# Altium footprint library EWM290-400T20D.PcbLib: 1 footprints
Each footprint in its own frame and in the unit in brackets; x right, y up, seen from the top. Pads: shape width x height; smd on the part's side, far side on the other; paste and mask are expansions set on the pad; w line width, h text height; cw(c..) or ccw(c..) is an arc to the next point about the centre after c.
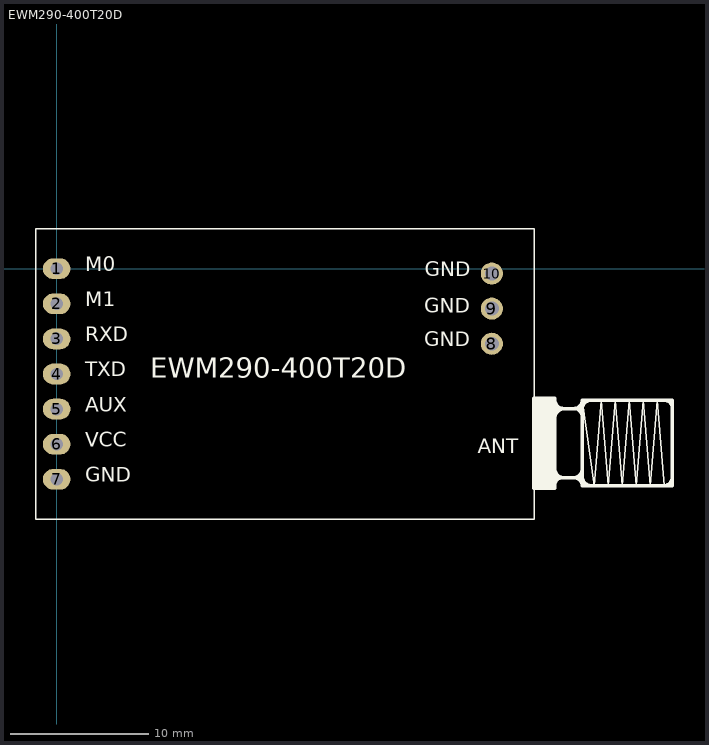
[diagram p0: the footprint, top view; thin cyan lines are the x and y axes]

## EWM290-400T20D [mm] "36mm*21mm-D/SMA长度12.5mm"
pads (10):
  oval 2x1.5 hole 0.9: 1(0,0) 2(0,-2.54) 3(0,-5.08) 4(0,-7.62) 5(0,-10.16) 6(0,-12.7) 7(0,-15.24)
  round 1.6 hole 1: 8(31.49,-5.43) 9(31.49,-2.89) 10(31.49,-0.35)
Top Overlay:
  rectangle: 34.54,-15.87 36.04,-9.37
  rectangle: 34.54,-15.865 36.04,-9.365
  lines w0.1: 38.89,-15.72 39.41,-9.52 ; 38.89,-15.72 38.04,-9.52 38.89,-15.72 ; 38.89,-15.72 39.41,-9.52 ; 39.41,-9.52 39.92,-15.72 ; 39.41,-9.52 39.92,-15.72 ; 39.92,-15.72 40.43,-9.52 ; 39.92,-15.72 40.43,-9.52 ; 40.43,-9.52 40.91,-15.72 ; 40.43,-9.52 40.91,-15.72 ; 40.91,-15.72 41.43,-9.52 ; 40.91,-15.72 41.43,-9.52 ; 41.43,-9.52 41.94,-15.72 ; 41.43,-9.52 41.94,-15.72 ; 41.94,-15.72 42.43,-9.52 ; 41.94,-15.72 42.43,-9.52 ; 42.43,-9.52 42.95,-15.72 ; 42.43,-9.52 42.95,-15.72 ; 42.95,-15.72 43.47,-9.52 ; 42.95,-15.72 43.47,-9.52 ; 43.47,-9.52 43.98,-15.72 43.47,-9.52 ; -1.51,-18.12 34.558,-18.12 34.558,2.88 -1.51,2.88 -1.51,-18.12
  lines w0.254: 34.54,-15.87 36.04,-15.87 ; 34.54,-15.87 34.54,-9.37 ; 34.54,-15.87 36.04,-15.87 ; 34.54,-15.87 34.54,-9.37 ; 34.54,-9.37 36.04,-9.37 ; 34.54,-9.37 36.04,-9.37 ; 36.04,-15.87 36.04,-9.37 ; 36.04,-15.87 36.04,-9.37 ; 36.04,-14.47 ccw(c36.69,-14.47) 36.69,-15.12 ; 36.04,-14.47 ccw(c36.69,-14.47) 36.69,-15.12 ; 36.04,-14.47 36.04,-14.1 36.04,-14.47 ; 36.04,-10.82 cw(c36.74,-10.82) 36.74,-10.12 ; 36.04,-10.82 cw(c36.74,-10.82) 36.74,-10.12 ; 36.04,-10.82 36.04,-11.74 36.04,-10.82 ; 36.04,-9.49 ccw(c36.67,-9.49) 36.67,-10.12 ; 36.04,-9.49 ccw(c36.67,-9.49) 36.67,-10.12 ; 36.04,-9.49 36.04,-9.37 ; 36.04,-9.49 36.04,-9.37 ; 36.59,-15.12 ccw(c36.59,-15.67) 36.04,-15.67 cw(c36.59,-15.67) 36.59,-15.12 ; 36.59,-15.12 37.44,-15.12 ; 36.59,-15.12 37.44,-15.12 ; 36.67,-10.12 37.44,-10.12 ; 36.67,-10.12 37.44,-10.12 ; 36.69,-15.12 37.41,-15.12 ; 36.69,-15.12 37.41,-15.12 ; 36.74,-10.12 37.44,-10.12 ; 36.74,-10.12 37.44,-10.12 ; 37.41,-15.12 ccw(c37.41,-14.49) 38.04,-14.49 cw(c37.41,-14.49) 37.41,-15.12 ; 37.44,-15.12 cw(c37.44,-15.72) 38.04,-15.72 ; 37.44,-15.12 cw(c37.44,-15.72) 38.04,-15.72 ; 37.44,-10.12 cw(c37.44,-10.72) 38.04,-10.72 ccw(c37.44,-10.72) 37.44,-10.12 ; 37.44,-10.12 ccw(c37.44,-9.52) 38.04,-9.52 ; 37.44,-10.12 ccw(c37.44,-9.52) 38.04,-9.52 ; 38.04,-15.72 38.04,-9.52 ; 38.04,-15.72 44.54,-15.72 ; 38.04,-15.72 38.04,-9.52 ; 38.04,-15.72 44.54,-15.72 ; 38.04,-9.52 44.54,-9.52 ; 38.04,-9.52 44.54,-9.52 ; 38.72,-15.72 cw(c38.72,-15.04) 38.04,-15.04 ccw(c38.72,-15.04) 38.72,-15.72 ; 38.72,-15.72 38.87,-15.72 38.72,-15.72 ; 43.92,-15.72 ccw(c43.92,-15.1) 44.54,-15.1 cw(c43.92,-15.1) 43.92,-15.72 ; 43.92,-15.72 43.69,-15.72 43.92,-15.72 ; 44,-9.52 cw(c44,-10.06) 44.54,-10.06 ccw(c44,-10.06) 44,-9.52 ; 44,-9.52 43.6,-9.52 44,-9.52 ; 44.54,-15.72 44.54,-9.52 ; 44.54,-15.72 44.54,-9.52 ; 35.87,-15.12 38.04,-15.12 35.87,-15.12 ; 36.04,-10.12 38.04,-10.12 36.04,-10.12 ; 38.04,-10.13 cw(c38.65,-10.13) 38.65,-9.52 ccw(c38.65,-10.13) 38.04,-10.13
  text "GND" at 2.063,-15.78 h1.8
  text "VCC" at 2.063,-13.24 h1.8
  text "AUX" at 2.063,-10.7 h1.8
  text "TXD" at 2.063,-8.16 h1.8
  text "RXD" at 2.063,-5.62 h1.8
  text "M1" at 2.063,-3.08 h1.8
  text "M0" at 2.063,-0.54 h1.8
  text "ANT" at 30.48,-13.716 h1.8
  text "GND" at 26.647,-0.921 h1.8
  text "GND" at 26.616,-3.556 h1.8
  text "GND" at 26.616,-5.969 h1.8
  text "EWM290-400T20D" at 6.771,-8.382 h2.5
